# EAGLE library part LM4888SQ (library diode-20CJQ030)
National's LM4888 Dual 2.1W Audio Amplifier Plus Stereo Headphone & 3D Enhancement Description: The LM4888 is a dual bridge-connected audio power amplifier which, when connected to a 5V supply, will deliver 2.1W to a 4Ohm load (Note 1) or 2.4W to a 3Ohm load (Note 2) with less than 1.0% THD+N. A user selectable 'National 3D Enhancement' mode provides enhanced stereo imaging. The LM4888SQ also has two separate HP (headphone) enable inputs, each having different logic level thresholds. Either HP enable input activates the single ended headphone mode and disables the BTL output mode. The HP Sense input is for use with a normal stereo headphone jack. The remaining input, HP Logic, accepts standard logic level thresholds. Boomer audio power amplifiers were designed specifically to provide high quality output power from a surface mount package while requiring few external components. To simplify audio system design, the LM4888SQ combines dual bridge speaker amplifiers and stereo headphone amplifiers on one chip. The LM4888SQ features a low-power consumption shutdown mode and thermal shutdown protection. It also utilizes circuitry to reduce 'clicks and pops' during device turn-on. Key Specifications: PO at 1% THD+N, VDD = 5V - RL = 3Ohm 2.4W (typ) - RL = 4Ohm 2.1W (typ) - RL = 8Ohm 1.3W (typ) Single-ended mode THD+N at 75mW into 32Ohm (5V, 1kHz) 0.01% (typ) Shutdown current 0.04uA (typ) Supply voltage range 2.7V to 5.5V PSRR at 217Hz 85dB (typ) Features: National 3D Enhancement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
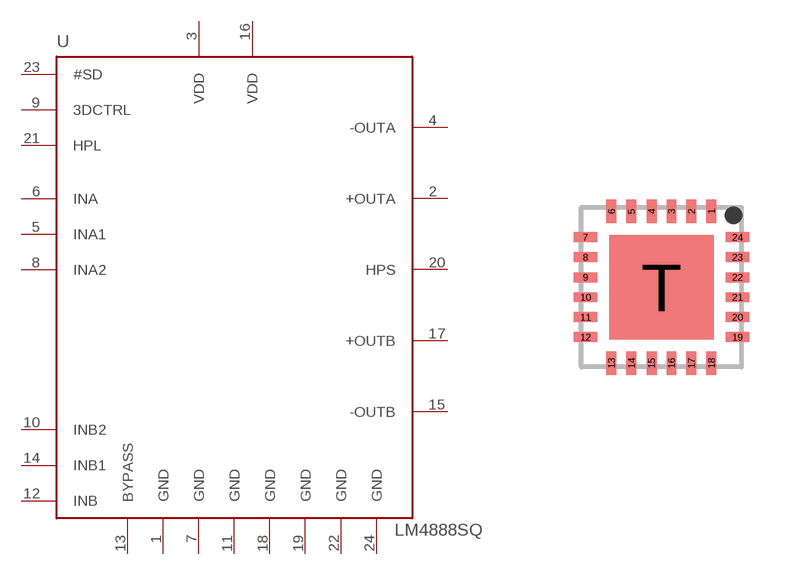
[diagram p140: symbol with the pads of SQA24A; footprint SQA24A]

Designator prefix U

## LM4888SQ  [SQA24A]
1  GND  pwr
2  +OUTA  out
3  VDD  pwr
4  -OUTA  out
5  INA1  in
6  INA  in
7  GND  pwr
8  INA2  in
9  3DCTRL  in
10  INB2  in
11  GND  pwr
12  INB  in
13  BYPASS
14  INB1  in
15  -OUTB  out
16  VDD  pwr
17  +OUTB  out
18  GND  pwr
19  GND  pwr
20  HPS  in
21  HPL  in
22  GND  pwr
23  #SD  in
24  GND  pwr

## Footprint SQA24A (pad centres in mm)
smd 0.25 x 0.6: 1 1.25,1.9; 2 0.75,1.9; 3 0.25,1.9; 4 -0.25,1.9; 5 -0.75,1.9; 6 -1.25,1.9; 13 -1.25,-1.9; 14 -0.75,-1.9; 15 -0.25,-1.9; 16 0.25,-1.9; 17 0.75,-1.9; 18 1.25,-1.9
smd 0.6 x 0.25: 7 -1.9,1.25; 8 -1.9,0.75; 9 -1.9,0.25; 10 -1.9,-0.25; 11 -1.9,-0.75; 12 -1.9,-1.25; 19 1.9,-1.25; 20 1.9,-0.75; 21 1.9,-0.25; 22 1.9,0.25; 23 1.9,0.75; 24 1.9,1.25
smd 2.6 x 2.6: T 0,0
